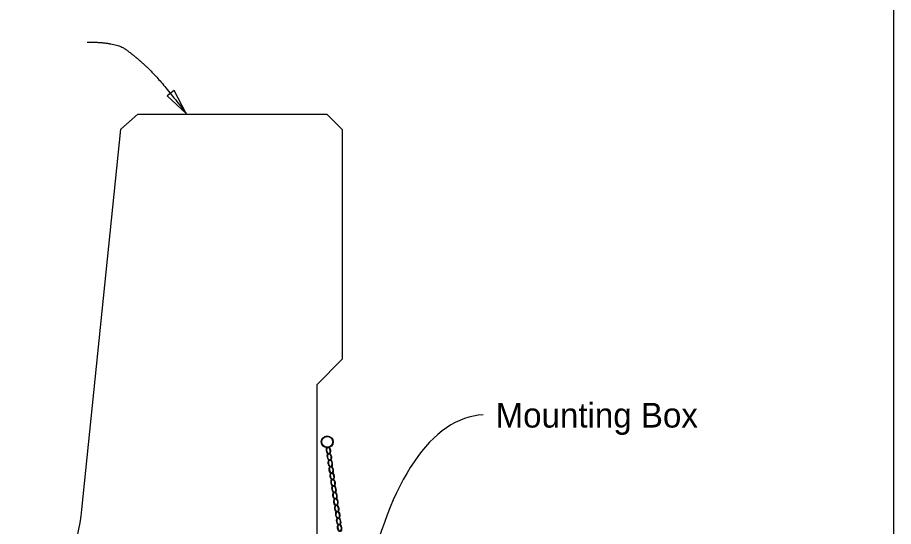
# Model space of a CAD drawing. Extents: x 83976.6 to 84012, y 72958.9 to 72975.6.
# Drawn here: x 83993.542 to 83997.111, y 72966.618 to 72968.694 of the extents above; entities that cross this region are included whole.
import ezdxf

# ---------------------------------------------------------------- set-up
doc = ezdxf.new("R2010")
doc.units = 0
for name, color, linetype in [('DSTitle', 7, 'Continuous'), ('Patterning', 7, 'Continuous'), ('RefPtStaTie', 7, 'Continuous'), ('SheetLines_dp', 7, 'Continuous'), ('SupstrConc', 7, 'Continuous')]:
    doc.layers.add(name, color=color, linetype=linetype)

msp = doc.modelspace()

# ---------------------------------------------------------------- linework, layer by layer
at = {"layer": 'DSTitle'}
for radius in [0.0241, 0.0222]:
    msp.add_circle((83994.8039, 72966.9637), radius, dxfattribs=at)
for centre, major_axis, ratio in [((83994.8088, 72966.9285), (-0.0022, 0.0152), 0.530594), ((83994.8088, 72966.9285), (-0.0019, 0.0131), 0.458548), ((83994.8126, 72966.9022), (-0.0022, 0.0152), 0.530594), ((83994.8126, 72966.9022), (-0.0019, 0.0131), 0.458548), ((83994.8164, 72966.8759), (-0.0022, 0.0152), 0.530594), ((83994.8164, 72966.8759), (-0.0019, 0.0131), 0.458548), ((83994.8202, 72966.8496), (-0.0022, 0.0152), 0.530594), ((83994.8202, 72966.8496), (-0.0019, 0.0131), 0.458548), ((83994.824, 72966.8233), (-0.0022, 0.0152), 0.530594), ((83994.824, 72966.8233), (-0.0019, 0.0131), 0.458548), ((83994.8278, 72966.797), (-0.0022, 0.0152), 0.530594), ((83994.8278, 72966.797), (-0.0019, 0.0131), 0.458548), ((83994.8315, 72966.7708), (-0.0022, 0.0152), 0.530594), ((83994.8315, 72966.7708), (-0.0019, 0.0131), 0.458548), ((83994.8353, 72966.7445), (-0.0022, 0.0152), 0.530594), ((83994.8353, 72966.7445), (-0.0019, 0.0131), 0.458548), ((83994.8391, 72966.7182), (-0.0022, 0.0152), 0.530594), ((83994.8391, 72966.7182), (-0.0019, 0.0131), 0.458548), ((83994.8429, 72966.6919), (-0.0022, 0.0152), 0.530594), ((83994.8429, 72966.6919), (-0.0019, 0.0131), 0.458548), ((83994.8467, 72966.6656), (-0.0022, 0.0152), 0.530594), ((83994.8467, 72966.6656), (-0.0019, 0.0131), 0.458548), ((83994.8505, 72966.6393), (-0.0022, 0.0152), 0.530594), ((83994.8505, 72966.6393), (-0.0019, 0.0131), 0.458548), ((83994.8542, 72966.613), (-0.0022, 0.0152), 0.530594), ((83994.8542, 72966.613), (-0.0019, 0.0131), 0.458548)]:
    msp.add_ellipse(centre, major_axis=major_axis, ratio=ratio, dxfattribs=at)
at = {"layer": 'RefPtStaTie'}
msp.add_lwpolyline([(83976.5859, 72973.1323), (83997.1112, 72973.1323), (83997.1112, 72960.1592), (83976.5859, 72960.1592)], close=True, dxfattribs=at)
at = {"layer": 'SheetLines_dp'}
msp.add_lwpolyline([(83994.229, 72968.3034), (83994.1796, 72968.3968), (83994.1516, 72968.3753)], close=True, dxfattribs=at)
msp.add_ellipse((83995.4874, 72965.7925), major_axis=(0.0485, -1.2809), ratio=0.439724, start_param=3.141585, end_param=4.215808, dxfattribs=at)
msp.add_open_spline([(83993.8254, 72968.5941), (83993.9416, 72968.5941), (83994.0223, 72968.536), (83994.1224, 72968.4423), (83994.229, 72968.3034)], degree=2, dxfattribs=at)
at = {"layer": 'SupstrConc'}
for p, q in [((83993.9629, 72968.2386), (83994.0318, 72968.3007)), ((83994.0318, 72968.3007), (83994.8026, 72968.3007)), ((83994.8026, 72968.3007), (83994.8651, 72968.2382)), ((83993.8042, 72966.6872), (83993.9629, 72968.2386)), ((83994.8651, 72968.2382), (83994.8651, 72967.3007)), ((83994.8651, 72967.3007), (83994.7609, 72967.1966)), ((83994.7609, 72967.1966), (83994.7609, 72965.6341))]:
    msp.add_line(p, q, dxfattribs=at)
msp.add_arc((83992.9752, 72966.772), 0.8333, 324.4623, 354.1605, dxfattribs=at)

# ---------------------------------------------------------------- texts
at = {"layer": 'Patterning'}
msp.add_text('Mounting Box', height=0.1008, dxfattribs=at).set_placement((83995.49, 72967.022))

doc.saveas('drawing.dxf')
